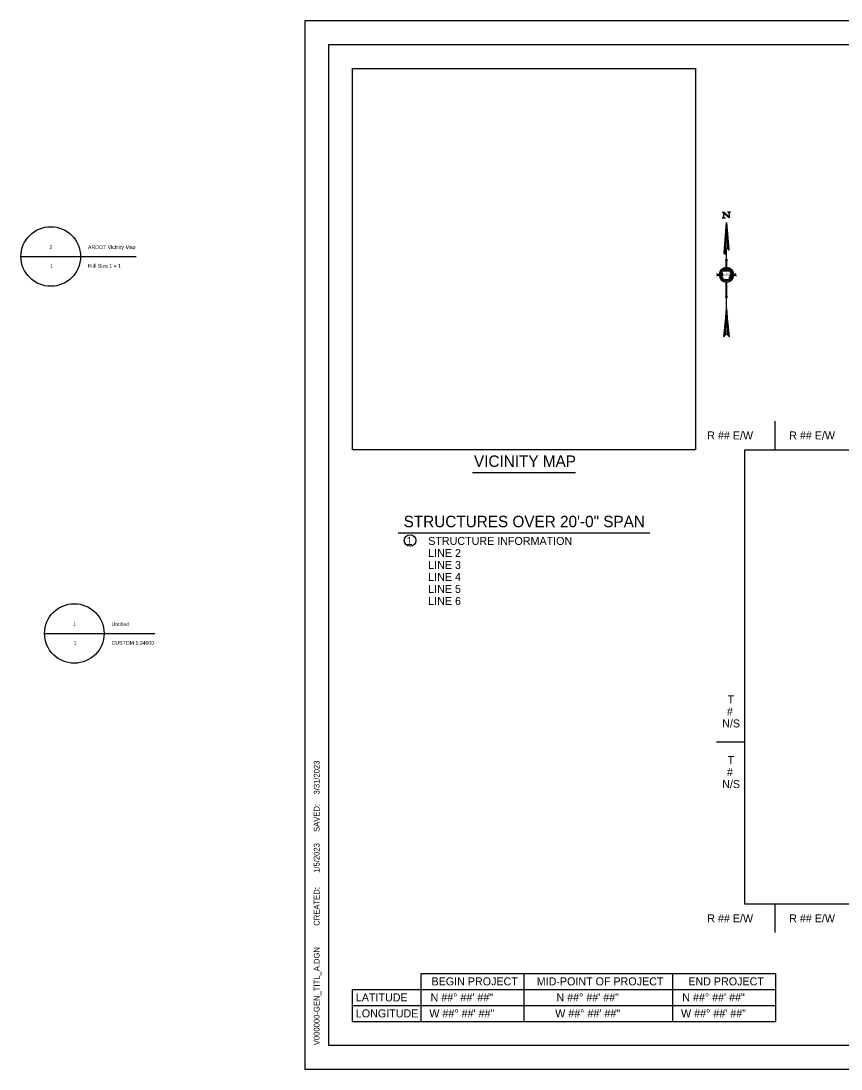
# Model space of a CAD drawing. Extents: x -0.25 to 1.42, y 0 to 0.92.
# Drawn here: x -0.248 to 0.469, y 0 to 0.917 of the extents above; entities that cross this region are included whole.
import ezdxf

# ---------------------------------------------------------------- set-up
doc = ezdxf.new("R2010")
doc.units = 0
for name, color, linetype in [('Default', 7, 'Continuous'), ('DSN_DRFT_DNC', 7, 'Continuous'), ('SHET_Annotations', 7, 'Continuous'), ('SHET_Border-Lines', 7, 'Continuous'), ('SHET_Border-Text', 7, 'Continuous')]:
    doc.layers.add(name, color=color, linetype=linetype)

msp = doc.modelspace()

# ---------------------------------------------------------------- linework, layer by layer
at = {"layer": 'Default'}
for p, q in [((-0.24803, 0.71066), (-0.19594, 0.71066)), ((-0.22176, 0.71066), (-0.14723, 0.71066)), ((-0.22744, 0.38096), (-0.17536, 0.38096)), ((-0.20117, 0.38096), (-0.13095, 0.38096))]:
    msp.add_line(p, q, dxfattribs=at)
for centre in [(-0.22198, 0.71066), (-0.2014, 0.38096)]:
    msp.add_circle(centre, 0.02604, dxfattribs=at)
at = {"layer": 'DSN_DRFT_DNC'}
for points in [[(0.04167, 0.875), (0.34167, 0.875), (0.34167, 0.54167), (0.04167, 0.54167)], [(0.38477, 0.54167), (1.0319, 0.54167), (1.0319, 0.1443), (0.38477, 0.1443)]]:
    msp.add_lwpolyline(points, close=True, dxfattribs=at)
at = {"layer": 'SHET_Annotations'}
for p, q in [((0.41091, 0.56667), (0.41091, 0.54167)), ((0.35977, 0.28626), (0.38477, 0.28626)), ((0.41091, 0.1443), (0.41091, 0.1193))]:
    msp.add_line(p, q, dxfattribs=at)
msp.add_circle((0.09208, 0.46227), 0.00509, dxfattribs=at)
at = {"layer": 'SHET_Border-Lines'}
for points in [[(0, 0), (1.41667, 0), (1.41667, 0.91667), (0, 0.91667)], [(0.02083, 0.02083), (1.39583, 0.02083), (1.39583, 0.89583), (0.02083, 0.89583)]]:
    msp.add_lwpolyline(points, close=True, dxfattribs=at)
at = {"layer": 'SHET_Border-Text'}
for p, q in [((0.36499, 0.74953), (0.36647, 0.74953)), ((0.36499, 0.74459), (0.36647, 0.74459)), ((0.36544, 0.74953), (0.37101, 0.74459)), ((0.36551, 0.74953), (0.37101, 0.74465)), ((0.36557, 0.74953), (0.37101, 0.74469)), ((0.36564, 0.74953), (0.37101, 0.74476)), ((0.3657, 0.74953), (0.37101, 0.7448)), ((0.36577, 0.74953), (0.37101, 0.74486)), ((0.36581, 0.74953), (0.37101, 0.74491)), ((0.36587, 0.74953), (0.37101, 0.74497)), ((0.36594, 0.74953), (0.37101, 0.74501)), ((0.366, 0.74953), (0.37101, 0.74508)), ((0.36607, 0.74953), (0.37101, 0.74514)), ((0.36613, 0.74953), (0.37101, 0.74519)), ((0.36615, 0.74953), (0.36615, 0.74459)), ((0.36619, 0.74953), (0.37101, 0.74525)), ((0.36624, 0.74953), (0.37101, 0.74529)), ((0.3663, 0.74953), (0.37101, 0.74536)), ((0.36637, 0.74953), (0.37101, 0.7454)), ((0.36643, 0.74953), (0.37101, 0.74546)), ((0.36647, 0.74953), (0.37101, 0.74549)), ((0.36647, 0.74459), (0.36771, 0.74459)), ((0.37069, 0.74953), (0.36945, 0.74953)), ((0.37215, 0.74953), (0.37069, 0.74953)), ((0.37101, 0.74953), (0.37101, 0.74459)), ((0.36729, 0.71301), (0.36729, 0.71506)), ((0.36767, 0.71301), (0.36767, 0.71603)), ((0.36866, 0.70038), (0.36866, 0.71699)), ((0.36666, 0.71333), (0.36666, 0.71397)), ((0.36699, 0.71307), (0.36699, 0.71461)), ((0.36744, 0.70763), (0.36825, 0.70763)), ((0.36825, 0.70117), (0.36825, 0.70763)), ((0.36906, 0.70119), (0.36906, 0.70763)), ((0.36906, 0.70763), (0.36988, 0.70763)), ((0.36358, 0.69226), (0.36358, 0.69712)), ((0.36377, 0.69192), (0.36377, 0.69748)), ((0.36399, 0.6916), (0.36399, 0.69781)), ((0.36418, 0.6913), (0.36418, 0.69813)), ((0.3644, 0.6911), (0.3644, 0.69838)), ((0.36459, 0.69087), (0.36459, 0.69858)), ((0.36504, 0.69554), (0.36465, 0.69802)), ((0.36465, 0.69802), (0.37206, 0.69802)), ((0.3648, 0.69802), (0.3648, 0.69879)), ((0.3648, 0.69066), (0.3648, 0.69699)), ((0.36499, 0.69802), (0.36499, 0.69896)), ((0.36521, 0.69802), (0.36521, 0.69915)), ((0.3654, 0.69802), (0.3654, 0.6993)), ((0.36562, 0.69802), (0.36562, 0.69943)), ((0.36581, 0.69802), (0.36581, 0.69956)), ((0.36602, 0.69802), (0.36602, 0.69967)), ((0.36622, 0.69802), (0.36622, 0.69978)), ((0.36643, 0.69802), (0.36643, 0.69986)), ((0.36662, 0.69802), (0.36662, 0.69995)), ((0.36681, 0.69802), (0.36681, 0.70003)), ((0.36703, 0.69802), (0.36703, 0.7001)), ((0.36722, 0.69802), (0.36722, 0.70016)), ((0.36744, 0.69802), (0.36744, 0.7002)), ((0.36763, 0.69802), (0.36763, 0.70025)), ((0.36784, 0.69802), (0.36784, 0.70027)), ((0.36804, 0.69802), (0.36804, 0.70031)), ((0.36825, 0.69802), (0.36825, 0.70033)), ((0.36844, 0.69802), (0.36844, 0.70035)), ((0.36866, 0.69802), (0.36866, 0.70038)), ((0.36885, 0.69802), (0.36885, 0.70033)), ((0.36906, 0.69802), (0.36906, 0.70033)), ((0.36926, 0.69802), (0.36926, 0.70029)), ((0.36947, 0.69802), (0.36947, 0.70027)), ((0.36966, 0.69802), (0.36966, 0.70023)), ((0.36988, 0.69802), (0.36988, 0.70018)), ((0.37007, 0.69802), (0.37007, 0.70014)), ((0.37026, 0.69802), (0.37026, 0.70008)), ((0.37048, 0.69802), (0.37048, 0.70001)), ((0.37067, 0.69802), (0.37067, 0.69995)), ((0.37088, 0.69802), (0.37088, 0.69986)), ((0.37108, 0.69802), (0.37108, 0.69978)), ((0.37129, 0.69802), (0.37129, 0.69967)), ((0.37148, 0.69802), (0.37148, 0.69956)), ((0.3717, 0.69802), (0.3717, 0.69943)), ((0.37189, 0.69802), (0.37189, 0.69928)), ((0.37219, 0.69736), (0.37191, 0.69678)), ((0.37191, 0.69678), (0.37317, 0.69678)), ((0.37206, 0.69802), (0.37206, 0.69802)), ((0.37206, 0.69802), (0.37223, 0.69772)), ((0.3721, 0.69798), (0.3721, 0.69915)), ((0.3721, 0.69678), (0.3721, 0.69714)), ((0.37223, 0.69772), (0.37219, 0.69736)), ((0.3723, 0.6968), (0.3723, 0.69896)), ((0.37251, 0.6968), (0.37251, 0.69881)), ((0.3727, 0.6968), (0.3727, 0.6986)), ((0.37292, 0.69678), (0.37292, 0.69838)), ((0.37311, 0.69678), (0.37311, 0.69817)), ((0.37317, 0.69678), (0.37334, 0.69656)), ((0.37332, 0.69663), (0.37332, 0.69787)), ((0.37352, 0.69185), (0.37352, 0.69753)), ((0.37371, 0.69224), (0.37371, 0.69716)), ((0.37392, 0.69271), (0.37392, 0.69669)), ((0.36054, 0.69511), (0.36054, 0.69592)), ((0.36054, 0.69511), (0.36217, 0.69511)), ((0.36054, 0.69348), (0.36054, 0.69429)), ((0.36054, 0.69429), (0.36217, 0.69429)), ((0.36318, 0.69333), (0.36318, 0.69603)), ((0.36337, 0.69269), (0.36337, 0.69665)), ((0.36487, 0.69179), (0.36504, 0.69554)), ((0.36519, 0.6916), (0.36487, 0.69179)), ((0.36499, 0.69509), (0.36499, 0.69564)), ((0.36499, 0.69048), (0.36499, 0.69168)), ((0.36581, 0.6916), (0.36519, 0.6916)), ((0.36521, 0.69031), (0.36521, 0.69158)), ((0.3654, 0.69014), (0.3654, 0.69158)), ((0.36562, 0.69003), (0.36562, 0.69158)), ((0.36581, 0.69027), (0.36581, 0.6916)), ((0.37099, 0.69027), (0.36581, 0.69027)), ((0.36581, 0.68988), (0.36581, 0.69025)), ((0.36602, 0.68978), (0.36602, 0.69027)), ((0.36622, 0.68967), (0.36622, 0.69027)), ((0.36643, 0.68958), (0.36643, 0.69027)), ((0.36662, 0.6895), (0.36662, 0.69027)), ((0.36681, 0.68941), (0.36681, 0.69027)), ((0.36703, 0.68935), (0.36703, 0.69027)), ((0.36722, 0.68929), (0.36722, 0.69027)), ((0.36744, 0.68924), (0.36744, 0.69027)), ((0.36763, 0.68918), (0.36763, 0.69027)), ((0.36784, 0.68916), (0.36784, 0.69027)), ((0.36804, 0.68913), (0.36804, 0.69027)), ((0.36825, 0.68909), (0.36825, 0.69027)), ((0.36825, 0.6755), (0.36825, 0.68824)), ((0.36844, 0.68907), (0.36844, 0.69027)), ((0.36866, 0.68907), (0.36866, 0.69027)), ((0.36866, 0.66511), (0.36866, 0.68903)), ((0.36885, 0.68907), (0.36885, 0.69027)), ((0.36906, 0.68909), (0.36906, 0.69027)), ((0.36906, 0.6755), (0.36906, 0.68824)), ((0.36926, 0.68911), (0.36926, 0.69027)), ((0.36947, 0.68913), (0.36947, 0.69027)), ((0.36966, 0.68918), (0.36966, 0.69027)), ((0.36988, 0.68922), (0.36988, 0.69027)), ((0.37007, 0.68926), (0.37007, 0.69027)), ((0.37026, 0.68933), (0.37026, 0.69027)), ((0.37048, 0.68937), (0.37048, 0.69027)), ((0.37067, 0.68946), (0.37067, 0.69027)), ((0.37088, 0.68954), (0.37088, 0.69027)), ((0.37125, 0.6908), (0.37099, 0.69027)), ((0.37108, 0.68963), (0.37108, 0.69038)), ((0.37129, 0.69267), (0.37116, 0.69168)), ((0.37116, 0.69168), (0.37125, 0.6908)), ((0.37174, 0.69344), (0.37129, 0.69267)), ((0.37129, 0.68973), (0.37129, 0.6925)), ((0.37148, 0.68984), (0.37148, 0.69292)), ((0.3717, 0.68997), (0.3717, 0.69329)), ((0.37202, 0.69402), (0.37174, 0.69344)), ((0.37189, 0.6901), (0.37189, 0.6937)), ((0.37245, 0.69464), (0.37202, 0.69402)), ((0.3721, 0.69025), (0.3721, 0.69408)), ((0.3723, 0.69042), (0.3723, 0.69438)), ((0.37268, 0.6953), (0.37245, 0.69464)), ((0.37251, 0.69059), (0.37251, 0.69479)), ((0.37268, 0.6953), (0.3729, 0.69584)), ((0.3727, 0.6908), (0.3727, 0.69532)), ((0.37326, 0.69629), (0.3729, 0.69584)), ((0.37292, 0.69102), (0.37292, 0.69584)), ((0.37311, 0.69128), (0.37311, 0.69609)), ((0.37334, 0.69656), (0.37326, 0.69629)), ((0.37332, 0.69155), (0.37332, 0.69641)), ((0.37412, 0.6934), (0.37412, 0.69605)), ((0.37512, 0.69511), (0.37675, 0.69511)), ((0.37512, 0.69429), (0.37675, 0.69429)), ((0.37675, 0.69511), (0.37675, 0.69592)), ((0.37675, 0.69429), (0.37675, 0.69348)), ((0.36744, 0.6755), (0.36825, 0.6755)), ((0.36906, 0.6755), (0.36988, 0.6755)), ((0.36866, 0.66511), (0.3661, 0.64052)), ((0.37113, 0.64033), (0.36866, 0.66511)), ((0.3661, 0.64052), (0.36866, 0.64306)), ((0.36866, 0.64306), (0.37113, 0.64033)), ((0.14667, 0.52167), (0.23667, 0.52167)), ((0.08167, 0.46888), (0.30167, 0.46888)), ((0.10167, 0.04167), (0.10167, 0.08367)), ((0.10167, 0.08367), (0.41167, 0.08367)), ((0.19167, 0.04167), (0.19167, 0.08367)), ((0.32167, 0.04167), (0.32167, 0.08367)), ((0.41167, 0.04167), (0.41167, 0.08367)), ((0.04167, 0.04167), (0.04167, 0.06967)), ((0.04167, 0.06967), (0.41167, 0.06967)), ((0.04167, 0.05567), (0.41167, 0.05567)), ((0.04167, 0.04167), (0.41167, 0.04167))]:
    msp.add_line(p, q, dxfattribs=at)
for points in [[(0.36544, 0.74459), (0.36615, 0.74544), (0.36679, 0.74459), (0.36671, 0.74463), (0.36553, 0.74463), (0.36613, 0.74538), (0.36669, 0.74467), (0.36562, 0.74465), (0.36613, 0.74529), (0.3666, 0.74471), (0.3657, 0.74469), (0.36613, 0.74523), (0.36649, 0.74476), (0.36583, 0.74474), (0.36615, 0.74516), (0.36639, 0.7448), (0.36592, 0.74478), (0.36613, 0.74508), (0.3663, 0.74484), (0.366, 0.74482), (0.36613, 0.74501), (0.36622, 0.74486), (0.36609, 0.74486), (0.36613, 0.74495), (0.36617, 0.74489), (0.36615, 0.74489)], [(0.3717, 0.74953), (0.37101, 0.74868), (0.37035, 0.74953), (0.37045, 0.74949), (0.37161, 0.74949), (0.37101, 0.74874), (0.37048, 0.74945), (0.37155, 0.74947), (0.37101, 0.74882), (0.37056, 0.7494), (0.37144, 0.74942), (0.37101, 0.74889), (0.37065, 0.74936), (0.37133, 0.74938), (0.37101, 0.74898), (0.37075, 0.74932), (0.37125, 0.74934), (0.37101, 0.74904), (0.37084, 0.74927), (0.37114, 0.7493), (0.37101, 0.7491), (0.37093, 0.74925), (0.37105, 0.74925), (0.37101, 0.74917), (0.37099, 0.74923), (0.37101, 0.74923)], [(0.36652, 0.71384), (0.36866, 0.74052), (0.3708, 0.71675)], [(0.36703, 0.71588), (0.36866, 0.74052), (0.37037, 0.7178)], [(0.36748, 0.71645), (0.36866, 0.74052), (0.36979, 0.71793)], [(0.36814, 0.71716), (0.36866, 0.74052), (0.36915, 0.71787)], [(0.36677, 0.64205), (0.36866, 0.66511), (0.37045, 0.64197)], [(0.36989, 0.6426), (0.36866, 0.66511), (0.36734, 0.64261)], [(0.36791, 0.64316), (0.36866, 0.66511), (0.3693, 0.64324)]]:
    msp.add_lwpolyline(points, dxfattribs=at)
for start, end in [(93.60728, 176.42391), (3.57609, 86.41459), (183.61351, 266.41233), (273.59889, 356.38649)]:
    msp.add_arc((0.36865, 0.6947), 0.00649, start, end, dxfattribs=at)
for start_param, end_param in [(2.681637, 5.778782), (2.292506, 2.677814), (5.778782, 6.897374)]:
    msp.add_ellipse((0.36865, 0.71525), major_axis=(-0.0019, -0.00211), ratio=0.467585, start_param=start_param, end_param=end_param, dxfattribs=at)

# ---------------------------------------------------------------- texts
at = {"layer": 'Default'}
for s, height, p in [('2', 0.00328, (-0.22314, 0.71722)), ('ARDOT Vicinity Map', 0.0032808, (-0.18943, 0.71722)), ('1', 0.00328, (-0.22261, 0.70081)), ('Full Size 1 = 1', 0.0032808, (-0.18943, 0.70081)), ('1', 0.00328, (-0.20225, 0.38752)), ('Untitled', 0.003281, (-0.16885, 0.38752)), ('1', 0.00328, (-0.20202, 0.37112)), ('CUSTOM 1:24000', 0.0032808, (-0.16885, 0.37112))]:
    msp.add_text(s, height=height, dxfattribs=at).set_placement(p)
at = {"layer": 'SHET_Annotations'}
for s, height, p in [('R ## E/W', 0.007, (0.35181, 0.55067)), ('R ## E/W', 0.007, (0.42341, 0.55067)), ('VICINITY MAP', 0.01, (0.14791, 0.52667)), ('1', 0.007, (0.08896, 0.45838)), ('STRUCTURE INFORMATION', 0.007, (0.10792, 0.45838)), ('LINE 2', 0.007, (0.10792, 0.44788)), ('LINE 3', 0.007, (0.10792, 0.43738)), ('LINE 4', 0.007, (0.10792, 0.42688)), ('LINE 5', 0.007, (0.10792, 0.41638)), ('LINE 6', 0.007, (0.10792, 0.40588)), ('T', 0.007, (0.36963, 0.31976)), ('#', 0.007, (0.36899, 0.30926)), ('N/S', 0.007, (0.36488, 0.29876)), ('T', 0.007, (0.36963, 0.26676)), ('#', 0.007, (0.36899, 0.25626)), ('N/S', 0.007, (0.36488, 0.24576)), ('R ## E/W', 0.007, (0.35181, 0.1283)), ('R ## E/W', 0.007, (0.42341, 0.1283)), ('N ##° ##\' ##"', 0.007, (0.10997, 0.05917)), ('N ##° ##\' ##"', 0.007, (0.21997, 0.05917)), ('N ##° ##\' ##"', 0.007, (0.32997, 0.05917)), ('W ##° ##\' ##"', 0.007, (0.10891, 0.04517)), ('W ##° ##\' ##"', 0.007, (0.21891, 0.04517)), ('W ##° ##\' ##"', 0.007, (0.32891, 0.04517))]:
    msp.add_text(s, height=height, dxfattribs=at).set_placement(p)
at = {"layer": 'SHET_Border-Text'}
for s, height, p in [('A  DOT', 0.001816, (0.36497, 0.69378)), ('R', 0.00121, (0.36658, 0.69378)), ('STRUCTURES OVER 20\'-0" SPAN', 0.01, (0.08643, 0.47388)), ('BEGIN PROJECT', 0.007, (0.11082, 0.07317)), ('MID-POINT OF PROJECT', 0.007, (0.20277, 0.07317)), ('END PROJECT', 0.007, (0.33526, 0.07317)), ('LATITUDE', 0.007, (0.04467, 0.05917)), ('LONGITUDE', 0.007, (0.04467, 0.04517))]:
    msp.add_text(s, height=height, dxfattribs=at).set_placement(p)
for s, p in [('3/31/2023', (0.01292, 0.24008)), ('  SAVED: ', (0.01292, 0.20366)), ('1/5/2023', (0.01292, 0.17159)), ('     CREATED: ', (0.01292, 0.11601)), ('V000000-GEN_TITL_A.DGN', (0.01292, 0.02083))]:
    msp.add_text(s, height=0.005, rotation=90, dxfattribs=at).set_placement(p)

doc.saveas('drawing.dxf')
